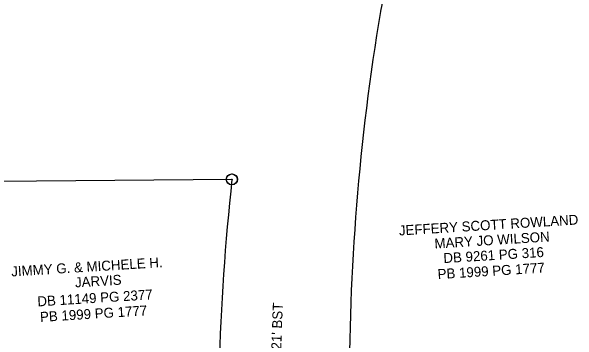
# Model space of a CAD drawing. Extents: x 2110969 to 2113691, y 670003 to 672285.
# Drawn here: x 2111867.6 to 2112095.2, y 670588.4 to 670720.8 of the extents above; entities that cross this region are included whole.
import ezdxf

# ---------------------------------------------------------------- set-up
doc = ezdxf.new("R2010")
doc.units = 0
for name, color, linetype in [('Exist Property Deed Book Text', 7, 'Continuous'), ('Exist Property Iron Pin CELL', 7, 'Continuous'), ('Exist Property Line', 7, 'Continuous'), ('Exist Property Owner Text', 7, 'Continuous'), ('Exist Right of Way Line', 7, 'Continuous'), ('Exist Roads EOP Text', 7, 'Continuous')]:
    doc.layers.add(name, color=color, linetype=linetype)

msp = doc.modelspace()

# ---------------------------------------------------------------- linework, layer by layer
at = {"layer": 'Exist Property Iron Pin CELL'}
for centre, radius in [((2111956.21, 670653.27), 2.2), ((2111956.21, 670653.27), 2.2), ((2111956.32, 670653.26), 2.2), ((2111956.32, 670653.26), 2.2), ((2111956.21, 670653.27), 0.0707), ((2111956.21, 670653.27), 0.0707), ((2111956.32, 670653.26), 0.0707), ((2111956.32, 670653.26), 0.0707)]:
    msp.add_circle(centre, radius, dxfattribs=at)
at = {"layer": 'Exist Property Line'}
msp.add_line((2111956.32, 670653.26), (2111777.37, 670651.74), dxfattribs=at)
at = {"layer": 'Exist Right of Way Line'}
for centre, radius, start, end in [((2112892.03, 670539.92), 894.47, 162.92448, 168.33205), ((2112897.97, 670571.58), 894.47, 170.39588, 180.45645), ((2112895.71, 670550.7), 944.98, 173.76908, 178.4087)]:
    msp.add_arc(centre, radius, start, end, dxfattribs=at)

# ---------------------------------------------------------------- texts
at = {"layer": 'Exist Property Deed Book Text'}
for s, p in [('DB 9261 PG 316', (2112041.4, 670619.6)), ('PB 1999 PG 1777', (2112039.07, 670613.16)), ('DB 11149 PG 2377', (2111878.22, 670602.19)), ('PB 1999 PG 1777', (2111879.28, 670595.96))]:
    msp.add_text(s, height=4, rotation=3.5509, dxfattribs=at).set_placement(p)
at = {"layer": 'Exist Property Owner Text'}
for s, p in [('JEFFERY SCOTT ROWLAND', (2112023.51, 670630.69)), ('MARY JO WILSON', (2112037.81, 670625.45)), ('JIMMY G. & MICHELE H.', (2111867.71, 670614.24)), ('JARVIS', (2111893.34, 670609.83))]:
    msp.add_text(s, height=4, rotation=3.5509, dxfattribs=at).set_placement(p)
at = {"layer": 'Exist Roads EOP Text'}
msp.add_text("SR 5330 FIELD HILL RD  21' BST", height=4, rotation=87.9251, dxfattribs=at).set_placement((2111973.82, 670522.41))

doc.saveas('drawing.dxf')
